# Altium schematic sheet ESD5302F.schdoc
size 127 x 101 mm
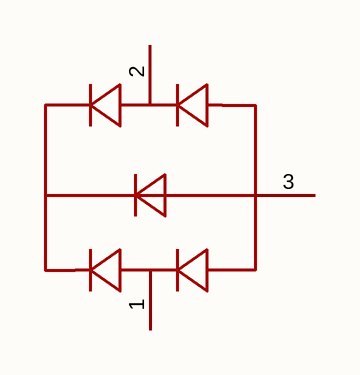
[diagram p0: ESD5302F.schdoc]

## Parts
D?  esd5302f  [SOT-23-3_L2.9-W1.3-P1.90-LS2.4-BR]  (value not drawn)

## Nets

Not connected (* = marked no-connect by the designer): D? 1 2 3

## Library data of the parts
D? = esd5302f: 极性:单向;反向截止电压(Vrwm):5V;钳位电压:14V;峰值脉冲电流(Ipp):4A@8/20us;峰值脉冲功率(Ppp):75W@8/20us;击穿电压:9V;; Manufacturer: TECH PUBLIC(台舟); AddInBom: yes; ModelId: c62791f0466c4ae2a892c056b845b0ca; ModelName: SOT-23-3P_L2.9-W1.3-H1.0-LS2.4-P0.95; ModelTransform: 98.425,114.173,0,180,0,0,0.0005,-0.0005,0; Polarity: 单向; Reverse Stand-Off Voltage (Vrwm): 5V; Clamping Voltage: 14V; Voltage - Breakdown: 9V; Reverse Leakage Current (Ir): 80nA; Number of Channels: 双路; level of protection: IEC 61000-4-2；IEC 61000-4-5; Type: ESD; Junction Capacitance: 0.5pF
